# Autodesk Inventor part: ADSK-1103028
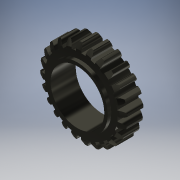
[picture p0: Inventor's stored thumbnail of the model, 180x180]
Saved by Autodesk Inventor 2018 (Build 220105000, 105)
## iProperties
Shininess: 41.0
Length Units: 11272
Angle Units: 11279
Time Units: 11290
Mass Units: 11286
Length Display Precision: 4
Angle Display Precision: 2
Compacted: True
Created: 2000-06
Part Number: ADSK-1103028
Document SubType Name: Modeling
Description: 24 TOOTH CLUTCH GEAR
Mass: 6.16542 g
Surface Area: 11.6587 cm^2
Volume: 0.786406 cm^3
Density: 7.84 g/cm^3
Material: Steel, High Strength Low Alloy
Appearance: Gunmetal
Density: 0.0
Volumn: 0.0
Area: 0.0
PropertySet Name: Model Information
Control State: 0
Master: False
Checked Out: False
Author: Autodesk, Inc.
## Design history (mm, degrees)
node "Extrusion1" dims "d2" = 5.08 (= Thickness), "d3" = 0
  sketch "Sketch2"
    geometry: C1 r 8.607 at (0, 0); 1 further point
    constraints: 1 centre point, 1 coincident
    dimensions: "d0" = 17.21326 diameter of C1 (= RD)
node "Extrusion2" dims "d17" = 6.35, "d18" = 0
  sketch "Sketch3"
    geometry: L1 (0, 0)-(0, 27.478); L2 (0, 9.525)-(-7.278, 9.525); L3 (0, 9.525)-(-4.075, 8.471); L4 (0.054, 9.221)-(0.051, 8.606); L5 (-0.675, 10.297)-(-0.563, 8.588); C1 r 8.607 at (0, 0) reference; A1 r 10.319 centre (0, 0) between (-0.371, 10.312) and (-0.675, 10.297); A2 r 9.525 centre (0, 0) between (0, 9.525) and (-0.623, 9.505); A3 r 9.222 centre (0, 0) between (-2.309, 8.928) and (0.054, 9.221); A4 r 8.607 centre (0, 0) between (0.051, 8.606) and (-0.563, 8.588); A5 r 2.381 centre (-2.309, 8.928) between (0.054, 9.221) and (-0.371, 10.312)
    constraints: 10 end point, 10 point on circle, 5 centre point, 5 point on line, 1 concentric, 1 perpendicular, 1 tangent, 1 vertical
    dimensions: "d4" = 20.6375 diameter of A1 (= OD); "d5" = 19.05 diameter of A2 (= PD); "d6" = 18.44321 diameter of A3 (= BC); "d7" = 17.21326 diameter of A4 (= RD); "d8" = 14.5 deg angle of L2 L3 (= AN); "d9" = 4.7625 diameter of A5 (= 0.25 x PD); "d10" = 0.62309 distance of L2.start A2.end (= 0.5 x CT)
node "Mirror1"
node "Extrusion4" dims "d25" = 0.8636, "d26" = 0
  sketch "Sketch5"
    geometry: C1 r 7.144 at (0, 0); A1 r 10.319 centre (0, 0) between (-4.834, -9.116) and (-4.29, -9.385) reference
    constraints: 1 centre point, 1 coincident
    dimensions: "d30" = 14.2875 diameter of C1
node "Extrusion5" dims "d28" = 5.08, "d29" = 0
  sketch "Sketch6"
    geometry: C1 r 7.144 at (0, 0) reference; C2 r 6.35 at (0, 0)
    constraints: 1 centre point, 1 coincident
    dimensions: "d27" = 12.7 diameter of C2
workaxis "Work Axis2"
workplane "Work Plane2"
  workpoint "Work Point1"
node "Revolution1" dims "d34" = 90 deg
  sketch "Sketch7"
    geometry: L1 (-10.314, -0.864)-(-9.049, -0.864); L2 (-9.049, -0.864)-(-10.319, -1.499); L3 (-10.319, -5.944)-(-9.049, -5.944); L4 (-9.049, -5.944)-(-10.319, -5.309); L5 (0, 1.189)-(0, -7.132) reference; L6 (-10.319, -0.864)-(-10.319, -5.944) reference; L7 (-10.314, -0.864)-(-10.319, -0.864)
    constraints: 10 end point, 2 perpendicular, 2 point on line, 1 equal length, 1 parallel
    dimensions: "d31" = 0.635 distance of L1.start L2.end; "d33" = 0.635 distance from line of L4.end L3 (= d31); "d35" = 1.27 distance from line of L6 L1.end (= 2 x d31)
body "Solid1"
node "Circular Pattern1" dims "d19" = 240 (= NM), "d21" = 360 deg
other parameters: "PD" = 19.05 [user parameter; used in 2 equation terms], "ADD" = 0.79375 [user parameter], "DED" = 0.91837 [user parameter], "CL" = 0.12462 [user parameter], "OD" = 20.6375 [user parameter; used in 1 equation term], "RD" = 17.21326 [user parameter; used in 2 equation terms], "BC" = 18.44321 [user parameter; used in 1 equation term], "CP" = 2.49364 [user parameter], "CT" = 1.24619 [user parameter; used in 1 equation term], "AN" = 14.5 deg [user parameter; used in 1 equation term], "d1" = 36.26326 [user parameter], "Thickness" = 5.08 [user parameter; used in 1 equation term], "d11" = 39.6875 [user parameter], "d12" = 38.1 [user parameter], "d13" = 36.88643 [user parameter], "d14" = 36.26326 [user parameter], "d15" = 14.5 deg [user parameter], "d16" = 1.24619 [user parameter]
